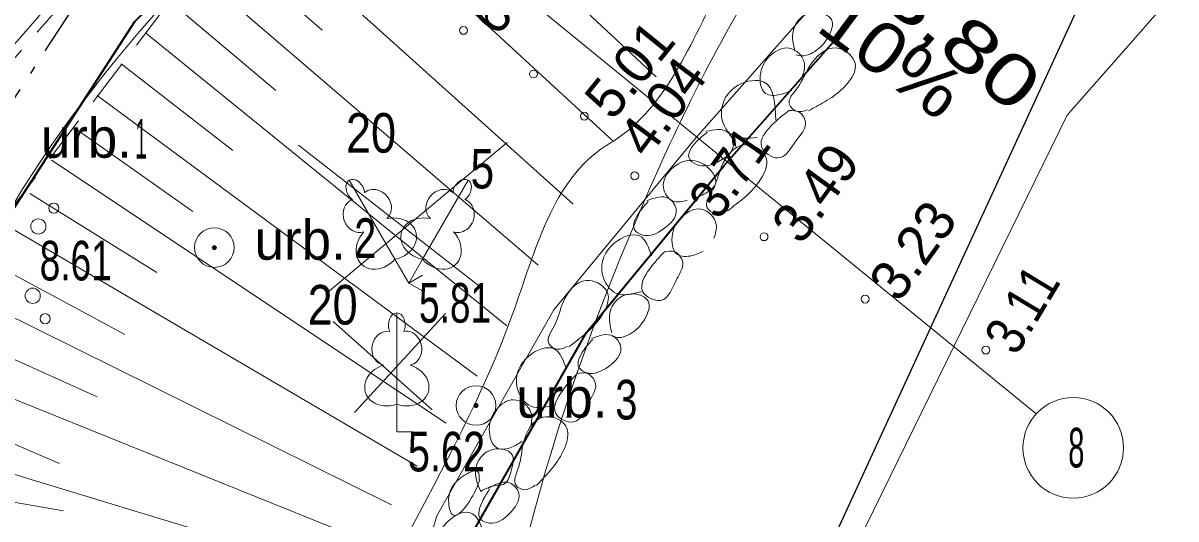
# Model space of a CAD drawing. Extents: x -1320 to -1174, y 762 to 862.
# Drawn here: x -1259.56 to -1244.99, y 797.2 to 803.46 of the extents above; entities that cross this region are included whole.
import ezdxf
from ezdxf.enums import TextEntityAlignment as Align

# ---------------------------------------------------------------- set-up
doc = ezdxf.new("R2010")
doc.units = 0
doc.header["$LTSCALE"] = 0.2
doc.linetypes.add('DOT_DASHED', pattern=[7.7, 5, -1.2, 0.3, -1.2])
doc.linetypes.add('MEDIUM_DASHED', pattern=[4.5, 3, -1.5])
for name, color, linetype, lineweight in [('1', 7, 'Continuous', 13), ('12', 7, 'Continuous', 13), ('19', 7, 'Continuous', 25), ('35', 7, 'Continuous', 25), ('5', 7, 'Continuous', 13), ('55', 7, 'Continuous', 13), ('6', 7, 'Continuous', 13), ('62', 7, 'Continuous', 13), ('63', 7, 'Continuous', 13)]:
    doc.layers.add(name, color=color, linetype=linetype, lineweight=lineweight)
doc.layers.add('8', color=7, linetype='Continuous')

msp = doc.modelspace()

# ---------------------------------------------------------------- hatches: boundary and pattern name
at = {"layer": '6'}
for points in [[(-1257.1137, 800.6234, 1), (-1257.1668, 800.6234, 1)], [(-1253.808, 798.6297, 1), (-1253.861, 798.6297, 1)]]:
    msp.add_hatch(color=256, dxfattribs=at).paths.add_polyline_path(points)

# ---------------------------------------------------------------- linework, layer by layer
at = {"layer": '1'}
for p, q in [((-1259.05, 808.547), (-1246.761, 798.528)), ((-1255.353, 806.325), (-1251.557, 802.778)), ((-1256.033, 805.592), (-1252.1, 801.969)), ((-1256.706, 804.853), (-1252.608, 801.173)), ((-1257.039, 804.48), (-1255.78, 803.368)), ((-1257.367, 804.103), (-1253.05, 800.403)), ((-1257.691, 803.721), (-1256.362, 802.606)), ((-1258.008, 803.335), (-1253.446, 799.634)), ((-1258.319, 802.943), (-1256.905, 801.848)), ((-1258.621, 802.545), (-1253.821, 799)), ((-1258.915, 802.14), (-1257.41, 801.079)), ((-1259.198, 801.728), (-1254.211, 798.406)), ((-1259.47, 801.308), (-1257.865, 800.311)), ((-1259.729, 800.881), (-1254.58, 797.862)), ((-1259.974, 800.445), (-1258.272, 799.527)), ((-1260.204, 800.001), (-1254.903, 797.374)), ((-1260.418, 799.549), (-1258.621, 798.738)), ((-1260.615, 799.09), (-1255.191, 796.905)), ((-1260.777, 798.617), (-1259.097, 797.898)), ((-1260.9, 798.133), (-1255.424, 796.475)), ((-1260.997, 797.642), (-1259.044, 797.299))]:
    msp.add_line(p, q, dxfattribs=at)
msp.add_circle((-1246.2897, 798.0951), 0.635, dxfattribs=at)
msp.add_spline([(-1235.8, 825.801), (-1237.913, 825.174), (-1239.203, 823.346), (-1241.709, 821.268), (-1246.557, 815.58), (-1256.526, 805.053), (-1260.592, 799.147), (-1261.416, 795.29), (-1262.742, 791.444), (-1262.206, 785.139)], degree=3, dxfattribs=at)
at = {"layer": '19', "lineweight": 13}
msp.add_spline([(-1253.457, 785.393), (-1253.726, 794.104), (-1251.637, 801.373), (-1250.122, 804.26), (-1247.608, 807.348), (-1239.437, 815.545), (-1236.508, 819.221), (-1228.799, 821.851), (-1223.357, 826.161), (-1220.079, 827.95)], degree=3, dxfattribs=at)
at = {"layer": '35', "lineweight": 35}
msp.add_lwpolyline([(-1225.362, 830.487), (-1237.056, 827.834), (-1243.981, 818.809), (-1250.833, 810.905), (-1258.147, 803.474), (-1260.339, 800.099), (-1261.472, 796.156), (-1261.529, 794.093), (-1263.29, 790.894)], dxfattribs=at)
at = {"layer": '5'}
for p, q in [((-1255.435, 801.475), (-1254.859, 800.477)), ((-1253.935, 801.475), (-1254.512, 800.477)), ((-1255.241, 801.319), (-1255.243, 801.319)), ((-1253.974, 801.229), (-1253.974, 801.23)), ((-1254.859, 800.477), (-1254.685, 800.176)), ((-1254.512, 800.477), (-1254.685, 800.176)), ((-1254.685, 800.176), (-1254.512, 800.276)), ((-1254.685, 800.176), (-1254.512, 800.076)), ((-1254.835, 799.798), (-1254.835, 798.645)), ((-1254.745, 799.566), (-1254.746, 799.567)), ((-1254.835, 798.645), (-1254.835, 798.298)), ((-1254.835, 798.298), (-1254.635, 798.298))]:
    msp.add_line(p, q, dxfattribs=at)
for centre, radius in [((-1259.167, 801.1215), 0.064), ((-1259.3635, 800.8898), 0.096), ((-1259.4346, 800.0153), 0.096), ((-1259.2771, 799.726), 0.064)]:
    msp.add_circle(centre, radius, dxfattribs=at)
for centre, major_axis, ratio, start_param, end_param in [((-1255.3604, 801.3451), (0.075, -0.1298), 0.707107, 0.9957007, 3.1378155), ((-1254.0097, 801.3451), (-0.075, -0.1298), 0.707107, 3.1453698, 5.2874846), ((-1255.3597, 801.3455), (0.075, -0.1298), 0.707107, 3.1453698, 5.2874846), ((-1255.1015, 801.1541), (0.1397, -0.1646), 0.861323, 6.2831853, 9.424778), ((-1254.2686, 801.1541), (-0.1397, -0.1646), 0.861323, 3.1415927, 6.2831853), ((-1254.0104, 801.3455), (-0.075, -0.1298), 0.707107, 0.9957007, 3.1378155), ((-1255.3238, 801.0258), (0.0727, -0.2033), 0.861323, 3.1415927, 6.2831853), ((-1254.0463, 801.0258), (-0.0727, -0.2033), 0.861323, 6.2831853, 9.424778), ((-1254.9039, 800.7344), (-0.3133, -0.071), 0.814445, 1.5311707, 4.712389), ((-1254.4662, 800.7344), (0.3133, -0.071), 0.814445, 1.5707963, 4.7520146), ((-1255.0591, 800.6448), (0.2182, 0.2358), 0.814445, 1.5707963, 4.7520146), ((-1254.311, 800.6448), (-0.2182, 0.2358), 0.814445, 1.5311707, 4.712389), ((-1254.8346, 799.6482), (0, -0.1499), 0.707107, 3.1453698, 5.2874846), ((-1254.8355, 799.6482), (0, -0.1499), 0.707107, 0.9957007, 3.1378155), ((-1254.9633, 799.3534), (-0.0387, -0.2124), 0.861323, 3.1415927, 6.2831853), ((-1254.7068, 799.3534), (0.0387, -0.2124), 0.861323, 6.2831853, 9.424778), ((-1254.9246, 798.8911), (0.3068, 0.0951), 0.814445, 1.5707963, 4.7520146), ((-1254.7455, 798.8911), (-0.3068, 0.0951), 0.814445, 1.5311707, 4.712389)]:
    msp.add_ellipse(centre, major_axis=major_axis, ratio=ratio, start_param=start_param, end_param=end_param, dxfattribs=at)
at = {"layer": '55'}
for points in [[(-1279.323, 790.175), (-1264.692, 791.666), (-1263.121, 794.463), (-1263.06, 799.299), (-1247.785, 816.834), (-1237.845, 829.32), (-1225.799, 831.912), (-1223.768, 834.184)], [(-1251.178, 781.943), (-1250.876, 788.586), (-1249.424, 796.058), (-1246.365, 802.296), (-1239.008, 810.653), (-1237.317, 812.435), (-1234.783, 813.781), (-1227.269, 819.96), (-1220.231, 823.644), (-1218.172, 824.289), (-1214.858, 828.794), (-1213.694, 830.71)]]:
    msp.add_lwpolyline(points, dxfattribs=at)
at = {"layer": '6'}
for centre, radius in [((-1253.993, 803.3662), 0.05), ((-1253.109, 802.8152), 0.05), ((-1252.466, 802.2832), 0.05), ((-1251.829, 801.5292), 0.05), ((-1257.14, 800.6236), 0.25), ((-1250.1961, 800.7611), 0.05), ((-1257.1402, 800.6234), 0.0265), ((-1248.9185, 799.9736), 0.05), ((-1247.3937, 799.3304), 0.05), ((-1253.8343, 798.6299), 0.25), ((-1253.8345, 798.6297), 0.0265)]:
    msp.add_circle(centre, radius, dxfattribs=at)
at = {"layer": '62'}
msp.add_spline([(-1254.434, 786.21), (-1255.853, 794.247), (-1253.373, 799.783), (-1252.196, 801.907), (-1252.103, 801.965), (-1250.675, 804.058), (-1247.791, 807.511), (-1245.419, 810.213), (-1244.186, 811.494), (-1242.939, 812.764), (-1240.149, 815.75), (-1236.129, 820.169), (-1233.075, 822.242), (-1235.394, 825.816)], degree=3, dxfattribs=at)
at = {"layer": '63'}
for p, q in [((-1256.079, 801.918), (-1253.781, 800.128)), ((-1253.443, 801.952), (-1255.707, 800.06)), ((-1254.22, 799.79), (-1255.369, 798.54)), ((-1255.639, 799.689), (-1254.389, 798.574))]:
    msp.add_line(p, q, dxfattribs=at)
at = {"layer": '63', "lineweight": 25}
msp.add_lwpolyline([(-1251.428, 785.238), (-1264.287, 784.95), (-1270.386, 788.761), (-1278.142, 789.522), (-1278.429, 820.376), (-1260.692, 834.371), (-1258.181, 840.695), (-1250.014, 845.483), (-1229.719, 840.992), (-1227.821, 835.408), (-1218.992, 825.806), (-1239.144, 811.691), (-1246.246, 803.626), (-1250.024, 795.415), (-1251.371, 785.665)], close=True, dxfattribs=at)
at = {"layer": '63'}
for points in [[(-1262.966, 796.388), (-1261.719, 800.729), (-1259.323, 804.418), (-1255.629, 808.17), (-1251.935, 811.923), (-1248.539, 815.84), (-1245.143, 819.757), (-1241.53, 824.466), (-1237.916, 829.176), (-1231.805, 830.562), (-1225.694, 831.949), (-1225.362, 830.487), (-1237.053, 827.834), (-1240.518, 823.322), (-1243.326, 819.676), (-1247.407, 814.857), (-1250.833, 810.905), (-1254.833, 806.84), (-1258.147, 803.474), (-1260.348, 800.104), (-1261.483, 796.15)], [(-1261.483, 796.15), (-1260.348, 800.104), (-1258.147, 803.474), (-1257.342, 804.291), (-1256.78, 804.862), (-1256.04, 805.612), (-1253.626, 808.067), (-1251.48, 810.249), (-1250.651, 811.111), (-1250.414, 811.388), (-1248.806, 813.242), (-1245.075, 817.511), (-1244.093, 818.684), (-1242.558, 820.667), (-1241.555, 821.963), (-1239.557, 824.569), (-1237.053, 827.834), (-1230.901, 829.229)], [(-1231.863, 823.367), (-1235.734, 819.766), (-1239.521, 815.019), (-1242.918, 811.201), (-1245.916, 807.839), (-1248.699, 804.681), (-1251.078, 801.983), (-1252.85, 799.838), (-1253.787, 798.196), (-1254.328, 797.239), (-1254.328, 797.239), (-1255.102, 794.624)]]:
    msp.add_lwpolyline(points, dxfattribs=at)
at = {"layer": '63', "linetype": 'MEDIUM_DASHED'}
for points in [[(-1265.079, 785.987), (-1263.807, 789.442), (-1261.536, 795.397), (-1260.86, 799.605), (-1256.627, 805.136), (-1246.564, 815.823), (-1241.769, 821.378), (-1239.214, 823.453), (-1237.177, 827.558), (-1234.848, 828.79), (-1231.517, 829.195), (-1224.557, 831.447)], [(-1247.437, 816.79), (-1257.209, 805.83), (-1262.318, 799.97), (-1262.654, 795.375), (-1263.503, 792.223), (-1265.015, 790.631), (-1268.643, 788.504)]]:
    msp.add_lwpolyline(points, dxfattribs=at)
at = {"layer": '63', "linetype": 'DOT_DASHED', "lineweight": 25}
for points in [[(-1225.528, 831.218), (-1237.486, 828.505), (-1244.562, 819.283), (-1251.384, 811.414), (-1258.735, 803.946), (-1261.029, 800.414), (-1262.219, 796.272), (-1262.274, 794.295), (-1264.33, 790.56), (-1266.742, 787.222)], [(-1254.918, 786.26), (-1254.605, 794.542), (-1253.865, 797.042), (-1252.437, 799.553), (-1250.698, 801.658), (-1245.95, 807.041), (-1239.139, 814.697), (-1235.363, 819.429), (-1232.239, 822.444), (-1231.619, 822.931), (-1231.44, 822.991), (-1229.31, 823.677), (-1223.125, 826.536)]]:
    msp.add_lwpolyline(points, dxfattribs=at)
at = {"layer": '63', "lineweight": 35}
msp.add_lwpolyline([(-1254.918, 786.26), (-1254.605, 794.542), (-1253.865, 797.042), (-1252.437, 799.553), (-1251.568, 800.606), (-1250.698, 801.658), (-1248.324, 804.35), (-1245.95, 807.041), (-1242.544, 810.869), (-1239.139, 814.697), (-1237.251, 817.063), (-1235.363, 819.429), (-1233.801, 820.936), (-1232.239, 822.444), (-1231.619, 822.931), (-1229.31, 823.677), (-1223.125, 826.536)], dxfattribs=at)
at = {"layer": '63'}
for points in [[(-1249.805, 803.104), (-1249.829, 803.356), (-1249.7, 803.549), (-1249.462, 803.582), (-1249.345, 803.503), (-1249.39, 803.276), (-1249.505, 803.137), (-1249.716, 803.044), (-1249.795, 803.056)], [(-1249.716, 802.776), (-1249.685, 802.949), (-1249.877, 803.142), (-1250.105, 803.059), (-1250.238, 802.828), (-1250.176, 802.57), (-1249.993, 802.555), (-1249.849, 802.609)], [(-1249.647, 802.363), (-1249.785, 802.345), (-1249.876, 802.43), (-1249.77, 802.646), (-1249.617, 802.918), (-1249.285, 803.145), (-1249.053, 802.976), (-1249.313, 802.539), (-1249.535, 802.405), (-1249.634, 802.35)], [(-1250.046, 802.234), (-1250.196, 802.712), (-1250.522, 802.674), (-1250.735, 802.314), (-1250.599, 802.041), (-1250.283, 802.016)], [(-1249.88, 802.353), (-1250.1, 802.168), (-1250.227, 801.899), (-1250.021, 801.756), (-1249.777, 801.992), (-1249.672, 802.186), (-1249.753, 802.333), (-1249.88, 802.353)], [(-1250.93, 802.092), (-1250.652, 802.077), (-1250.582, 801.916), (-1250.777, 801.708), (-1251.051, 801.672), (-1251.143, 801.756), (-1251.049, 801.961), (-1250.915, 802.079)], [(-1250.676, 801.094), (-1250.81, 801.055), (-1250.913, 801.125), (-1250.842, 801.355), (-1250.733, 801.647), (-1250.441, 801.923), (-1250.185, 801.793), (-1250.374, 801.32), (-1250.572, 801.153), (-1250.661, 801.084)], [(-1251.167, 801.221), (-1251.351, 801.213), (-1251.468, 801.381), (-1251.368, 801.615), (-1251.108, 801.724), (-1250.84, 801.557), (-1250.806, 801.439), (-1250.915, 801.322), (-1251.058, 801.246)], [(-1251.675, 801.216), (-1251.398, 801.244), (-1251.304, 801.096), (-1251.464, 800.86), (-1251.729, 800.782), (-1251.833, 800.851), (-1251.773, 801.068), (-1251.659, 801.205)], [(-1250.83, 800.743), (-1250.799, 800.916), (-1250.991, 801.109), (-1251.219, 801.026), (-1251.352, 800.795), (-1251.29, 800.537), (-1251.107, 800.522), (-1250.963, 800.576)], [(-1251.616, 800.518), (-1251.769, 800.77), (-1252.085, 800.682), (-1252.239, 800.293), (-1252.062, 800.045), (-1251.746, 800.069)], [(-1251.455, 800.569), (-1251.643, 800.352), (-1251.727, 800.066), (-1251.501, 799.957), (-1251.297, 800.228), (-1251.223, 800.436), (-1251.326, 800.569), (-1251.455, 800.569)], [(-1252.677, 799.381), (-1252.811, 799.342), (-1252.914, 799.412), (-1252.843, 799.642), (-1252.734, 799.934), (-1252.442, 800.21), (-1252.186, 800.08), (-1252.375, 799.607), (-1252.573, 799.44), (-1252.662, 799.371)], [(-1252.119, 799.549), (-1252.143, 799.801), (-1252.014, 799.994), (-1251.776, 800.027), (-1251.659, 799.948), (-1251.704, 799.721), (-1251.819, 799.582), (-1252.03, 799.489), (-1252.109, 799.501)], [(-1252.376, 799.476), (-1252.099, 799.504), (-1252.005, 799.356), (-1252.165, 799.12), (-1252.43, 799.042), (-1252.534, 799.111), (-1252.474, 799.328), (-1252.36, 799.465)], [(-1252.695, 799.094), (-1252.848, 799.346), (-1253.164, 799.258), (-1253.318, 798.869), (-1253.141, 798.621), (-1252.825, 798.645)], [(-1252.556, 799.034), (-1252.744, 798.817), (-1252.828, 798.531), (-1252.602, 798.422), (-1252.398, 798.693), (-1252.324, 798.901), (-1252.427, 799.034), (-1252.556, 799.034)], [(-1253.143, 798.367), (-1253.14, 798.543), (-1253.36, 798.703), (-1253.572, 798.585), (-1253.667, 798.335), (-1253.564, 798.091), (-1253.381, 798.105), (-1253.248, 798.181)], [(-1253.089, 797.626), (-1253.215, 797.566), (-1253.328, 797.618), (-1253.295, 797.857), (-1253.234, 798.162), (-1252.989, 798.481), (-1252.716, 798.394), (-1252.827, 797.897), (-1252.996, 797.7), (-1253.073, 797.618)], [(-1253.778, 797.553), (-1253.842, 797.798), (-1253.745, 798.009), (-1253.516, 798.08), (-1253.387, 798.02), (-1253.396, 797.789), (-1253.487, 797.634), (-1253.577, 797.621), (-1253.78, 797.544)], [(-1253.785, 797.693), (-1253.894, 797.458), (-1254.129, 797.248), (-1254.179, 797.391), (-1253.978, 797.751), (-1253.81, 797.793), (-1253.794, 797.693)], [(-1253.68, 797.582), (-1253.411, 797.654), (-1253.295, 797.523), (-1253.415, 797.264), (-1253.665, 797.145), (-1253.778, 797.197), (-1253.754, 797.42), (-1253.663, 797.574)], [(-1253.712, 796.935), (-1253.917, 797.279), (-1254.215, 797.142), (-1254.305, 796.734), (-1254.091, 796.517), (-1253.783, 796.591)]]:
    msp.add_spline(points, degree=3, dxfattribs=at)

# ---------------------------------------------------------------- texts
at = {"layer": '1', "width": 0.55}
msp.add_text('8', height=0.5, dxfattribs=at).set_placement((-1246.353, 797.848))
at = {"layer": '12'}
for s, width, p in [(' 20', 0.85, (-1255.635, 801.822)), (' 5', 0.8, (-1254.052, 801.37)), (' 20', 0.85, (-1256.12, 799.652))]:
    msp.add_text(s, height=0.5, dxfattribs=dict(at, width=width)).set_placement(p)
at = {"layer": '6'}
for p in [(-1259.333, 801.758), (-1256.632, 800.471), (-1253.326, 798.477)]:
    msp.add_text('urb.', height=0.5, dxfattribs=at).set_placement(p)
for s, width, p in [('1', 0.4, (-1258.0655, 801.748)), ('2', 0.75, (-1255.234, 800.494)), ('3', 0.75, (-1251.9355, 798.454))]:
    msp.add_text(s, height=0.5, dxfattribs=dict(at, width=width)).set_placement(p, align=Align.CENTER)
at = {"layer": '63'}
for s, rotation, width, p in [('3,80', 319.946, 1.35, (-1247.9039, 803.0174)), ('10%', 323.374, 1.15, (-1248.7684, 802.7901))]:
    msp.add_text(s, height=0.64, rotation=rotation, dxfattribs=dict(at, width=width)).set_placement(p, align=Align.CENTER)
at = {"layer": '8'}
for s, rotation, p in [(' 6.18', 48.595, (-1253.704, 803.132)), (' 5.01', 51.068, (-1252.226, 802.068)), (' 4.04', 53.579, (-1251.776, 801.584)), (' 3.49', 54.114, (-1249.834, 800.491)), (' 3.23', 54.373, (-1248.601, 799.763))]:
    msp.add_text(s, height=0.5, rotation=rotation, dxfattribs=at).set_placement(p)
for s, rotation, width, p in [(' 3.71', 55.025, 0.9, (-1250.862, 800.818)), (' 3.11', 58.945, 0.85, (-1247.09, 799.108))]:
    msp.add_text(s, height=0.5, rotation=rotation, dxfattribs=dict(at, width=width)).set_placement(p)
for s, width, p in [(' 8.61', 0.7, (-1259.477, 800.209)), (' 5.81', 0.7, (-1254.685, 799.676)), (' 5.62', 0.75, (-1254.835, 797.798))]:
    msp.add_text(s, height=0.5, dxfattribs=dict(at, width=width)).set_placement(p)

doc.saveas('drawing.dxf')
